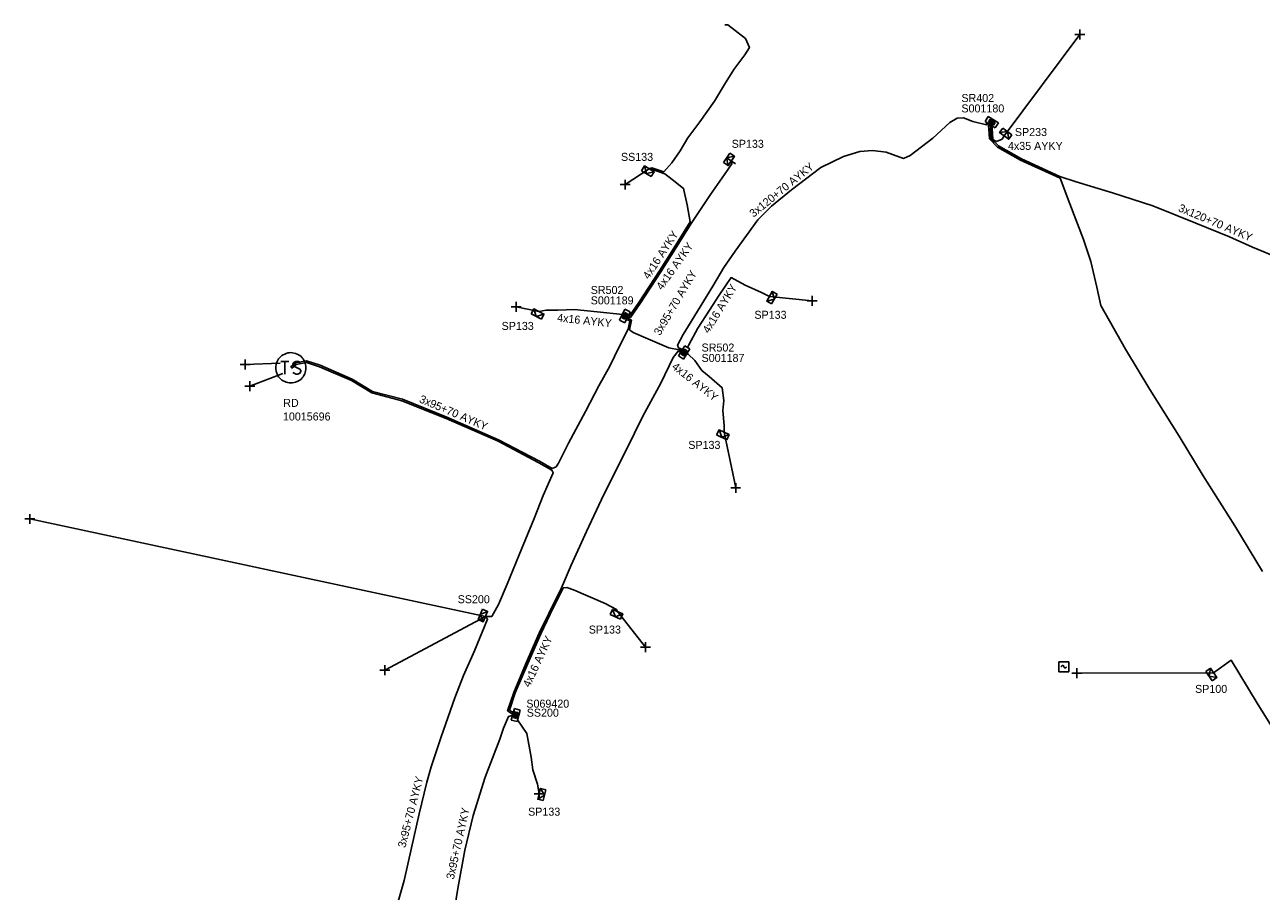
# Model space of a CAD drawing. Extents: x -763093 to -760976, y -1155572 to -1152009.
# Drawn here: x -761820.6 to -761666.2, y -1152363.5 to -1152255.3 of the extents above; entities that cross this region are included whole.
import ezdxf

# ---------------------------------------------------------------- set-up
doc = ezdxf.new("R2010")
doc.units = 0
for name, color, linetype in [('Vrstva 1', 7, 'Continuous'), ('Vrstva 25', 7, 'Continuous'), ('Vrstva 26', 7, 'Continuous'), ('Vrstva 27', 7, 'Continuous'), ('Vrstva 28', 7, 'Continuous'), ('Vrstva 29', 7, 'Continuous'), ('Vrstva 30', 7, 'Continuous'), ('Vrstva 31', 7, 'Continuous'), ('Vrstva 33', 7, 'Continuous'), ('Vrstva 34', 7, 'Continuous'), ('Vrstva 5', 7, 'Continuous'), ('Vrstva 52', 7, 'Continuous'), ('Vrstva 54', 7, 'Continuous'), ('Vrstva 59', 7, 'Continuous'), ('Vrstva 6', 7, 'Continuous'), ('Vrstva 8', 7, 'Continuous'), ('Vrstva 9', 7, 'Continuous')]:
    doc.layers.add(name, color=color, linetype=linetype)

# ---------------------------------------------------------------- blocks, each defined once
blk = doc.blocks.new('NN800')
at = {"layer": 'Vrstva 1'}
for points in [[(-0.44, 0.44), (0.44, -0.44)], [(-0.44, -0.44), (0.44, 0.44)]]:
    blk.add_lwpolyline(points, dxfattribs=at)
blk = doc.blocks.new('NN620')
at = {"layer": 'Vrstva 8'}
for points in [[(0.75, 0), (-0.75, 0)], [(-0.75, 0), (-0.75, -0.75)], [(0.75, -0.75), (0.75, 0)], [(-0.75, -0.75), (0.75, -0.75)], [(0.37, -0.18), (-0.38, -0.18)], [(-0.38, -0.18), (-0.38, -0.56)], [(-0.38, -0.56), (0.37, -0.56)], [(0.32, -0.23), (-0.33, -0.23)], [(-0.33, -0.23), (-0.33, -0.51)], [(-0.33, -0.51), (0.32, -0.51)], [(0.27, -0.27), (-0.28, -0.27)], [(-0.28, -0.27), (-0.28, -0.46)], [(-0.28, -0.46), (0.27, -0.46)], [(0.23, -0.32), (-0.23, -0.32)], [(-0.23, -0.32), (-0.23, -0.42)], [(-0.23, -0.42), (0.23, -0.42)], [(-0.19, -0.37), (0.19, -0.37)], [(0.23, -0.42), (0.23, -0.32)], [(0.27, -0.46), (0.27, -0.27)], [(0.32, -0.51), (0.32, -0.23)], [(0.37, -0.56), (0.37, -0.18)]]:
    blk.add_lwpolyline(points, dxfattribs=at)
blk = doc.blocks.new('NN630')
at = {"layer": 'Vrstva 9'}
for points in [[(0, -0.7), (-0.7, 0)], [(-0.7, -0.7), (-0.7, 0), (0.7, 0), (0.7, -0.7)], [(-0.7, -0.7), (0.7, -0.7)], [(0, -0.7), (0.7, 0)]]:
    blk.add_lwpolyline(points, dxfattribs=at)
blk = doc.blocks.new('NN740')
at = {"layer": 'Vrstva 1'}
for points in [[(0.62, 0.62), (-0.63, 0.62)], [(-0.63, 0.62), (-0.63, -0.63)], [(0, 0), (0, 0.01), (0, 0.03), (-0.01, 0.05), (-0.01, 0.06), (-0.02, 0.08), (-0.03, 0.09), (-0.04, 0.1), (-0.05, 0.11), (-0.06, 0.12), (-0.08, 0.13), (-0.09, 0.14), (-0.11, 0.14), (-0.12, 0.15), (-0.14, 0.15), (-0.15, 0.15), (-0.17, 0.15), (-0.18, 0.15), (-0.2, 0.15), (-0.21, 0.14), (-0.23, 0.13), (-0.24, 0.12), (-0.26, 0.11), (-0.27, 0.1), (-0.28, 0.09), (-0.29, 0.08), (-0.29, 0.06), (-0.3, 0.05), (-0.3, 0.03), (-0.31, 0.02), (-0.31, 0), (-0.31, 0)], [(0.62, -0.63), (0.62, 0.62)], [(-0.63, -0.63), (0.62, -0.63)], [(0, 0), (0, -0.02), (0, -0.03), (0.01, -0.05), (0.01, -0.06), (0.02, -0.08), (0.03, -0.09), (0.04, -0.1), (0.05, -0.11), (0.06, -0.12), (0.07, -0.13), (0.09, -0.14), (0.1, -0.15), (0.12, -0.15), (0.13, -0.15), (0.15, -0.15), (0.16, -0.15), (0.18, -0.15), (0.19, -0.15), (0.21, -0.14), (0.22, -0.14), (0.24, -0.13), (0.25, -0.12), (0.26, -0.11), (0.27, -0.09), (0.28, -0.08), (0.29, -0.07), (0.29, -0.05), (0.3, -0.04), (0.3, -0.02), (0.3, -0.01), (0.3, -0.01)]]:
    blk.add_lwpolyline(points, dxfattribs=at)
blk = doc.blocks.new('NN610')
at = {"layer": 'Vrstva 6'}
for points in [[(1.88, 0), (1.87, 0.2), (1.84, 0.39), (1.79, 0.58), (1.72, 0.77), (1.63, 0.94), (1.52, 1.11), (1.4, 1.26), (1.26, 1.4), (1.1, 1.53), (0.94, 1.63), (0.76, 1.72), (0.58, 1.8), (0.19, 1.88), (0.19, 1.88), (-0.01, 1.89), (-0.21, 1.88), (-0.4, 1.85), (-0.59, 1.8), (-0.78, 1.72), (-0.95, 1.63), (-1.12, 1.53), (-1.27, 1.4), (-1.41, 1.26), (-1.54, 1.11), (-1.64, 0.94), (-1.73, 0.77), (-1.8, 0.58), (-1.86, 0.39), (-1.89, 0.2), (-1.9, 0), (-1.89, -0.2), (-1.86, -0.39), (-1.8, -0.58), (-1.73, -0.77), (-1.64, -0.95), (-1.54, -1.11), (-1.41, -1.27), (-1.27, -1.41), (-1.12, -1.53), (-0.95, -1.64), (-0.78, -1.73), (-0.59, -1.8), (-0.4, -1.85), (-0.21, -1.88), (-0.01, -1.89), (0.19, -1.88), (0.39, -1.85), (0.58, -1.8), (0.76, -1.73), (0.94, -1.64), (1.1, -1.53), (1.26, -1.41), (1.4, -1.27), (1.52, -1.11), (1.63, -0.95), (1.72, -0.77), (1.79, -0.58), (1.84, -0.39), (1.87, -0.2), (1.88, 0)], [(-1.27, 0.78), (-0.26, 0.78)], [(-0.76, 0.78), (-0.76, -0.79)], [(1.19, 0.66), (0.94, 0.78), (0.62, 0.78), (0.37, 0.66), (0.24, 0.47), (0.24, 0.4), (0.37, 0.22), (1.12, -0.16), (1.25, -0.32), (1.25, -0.48), (1.12, -0.67), (0.87, -0.79), (0.62, -0.79), (0.49, -0.73), (0.24, -0.6)]]:
    blk.add_lwpolyline(points, dxfattribs=at)

msp = doc.modelspace()

# ---------------------------------------------------------------- linework, layer by layer
at = {"layer": 'Vrstva 5'}
for points in [[(-761700.49, -1152267.45), (-761700.47, -1152267.79), (-761702.2, -1152267.36), (-761703.36, -1152266.92), (-761704.13, -1152266.93), (-761705.05, -1152267.48), (-761707.19, -1152269.46), (-761710, -1152271.63), (-761710.83, -1152271.97), (-761713, -1152271.21), (-761714.72, -1152270.98), (-761716.3, -1152271.09), (-761718.33, -1152271.73), (-761721.19, -1152273.11), (-761724.84, -1152275.9), (-761727.33, -1152277.93), (-761729.06, -1152279.66), (-761731.86, -1152283.56), (-761733.3, -1152285.61), (-761734.68, -1152287.93), (-761736.24, -1152290.51), (-761738.37, -1152293.96), (-761739.06, -1152295.29), (-761738.95, -1152295.64), (-761738.45, -1152295.83)], [(-761665.98, -1152323.54), (-761669.44, -1152317.85), (-761673.42, -1152311.6), (-761676.42, -1152306.66), (-761680.09, -1152300.84), (-761683.11, -1152295.81), (-761686.2, -1152290.34), (-761686.68, -1152288.06), (-761687.44, -1152284.83), (-761688.36, -1152282.1), (-761690.08, -1152277.64), (-761691.29, -1152274.44), (-761696.22, -1152272.19), (-761699.11, -1152270.55), (-761700.09, -1152269.52), (-761700.18, -1152268.26), (-761700.25, -1152267.62)], [(-761660.25, -1152285.76), (-761661.13, -1152285.42), (-761663.93, -1152284.42), (-761667.23, -1152283.04), (-761670.12, -1152281.75), (-761674.31, -1152280.06), (-761679.7, -1152277.9), (-761684.72, -1152276.28), (-761689.26, -1152274.88), (-761691.3, -1152274.22), (-761696.12, -1152272.01), (-761698.99, -1152270.39), (-761699.89, -1152269.51), (-761699.98, -1152268.24), (-761700.03, -1152267.76)], [(-761699.81, -1152267.9), (-761699.78, -1152268.22), (-761699.68, -1152269.62), (-761699.24, -1152269.87), (-761698.52, -1152269.57), (-761698.27, -1152269.17)], [(-761745.28, -1152291.72), (-761744.97, -1152291.84), (-761743.73, -1152290.1), (-761741.18, -1152286.12), (-761739.58, -1152283.63), (-761737.38, -1152280.1), (-761734.95, -1152276.5), (-761733.21, -1152273.98), (-761732.29, -1152272.64), (-761732.35, -1152272.29)], [(-761745.19, -1152291.54), (-761745.05, -1152291.6), (-761743.89, -1152289.98), (-761741.34, -1152286.02), (-761739.74, -1152283.53), (-761737.49, -1152279.9), (-761737.87, -1152277.79), (-761738.31, -1152275.71), (-761739.75, -1152274.62), (-761740.65, -1152273.88), (-761742.32, -1152273.33), (-761742.6, -1152273.28)], [(-761737.85, -1152295.65), (-761737.66, -1152295.25), (-761736.53, -1152293.17), (-761735.06, -1152290.94), (-761733.87, -1152289.03), (-761732.39, -1152286.85), (-761730.61, -1152287.82), (-761728.57, -1152288.73), (-761727.59, -1152289.2)], [(-761756.4, -1152291.09), (-761755.48, -1152290.92), (-761754.03, -1152290.92), (-761751.93, -1152290.82), (-761749.1, -1152291.13), (-761745.91, -1152291.47)], [(-761745.45, -1152292.08), (-761745.03, -1152292.25), (-761745.25, -1152293.28), (-761746.35, -1152295.5), (-761747.55, -1152297.93), (-761748.91, -1152300.37), (-761750.58, -1152303.58), (-761752.7, -1152307.52), (-761753.95, -1152310.05), (-761754.25, -1152310.49), (-761754.74, -1152310.71), (-761756.32, -1152309.8), (-761761.42, -1152307.1), (-761767.91, -1152304.29), (-761773.44, -1152302.03), (-761777.18, -1152301.06), (-761779.7, -1152299.52), (-761783.71, -1152297.8), (-761785.42, -1152297.25), (-761786.78, -1152297.52), (-761787.43, -1152298.04)], [(-761738.56, -1152296), (-761738.88, -1152295.88), (-761740.15, -1152295.62), (-761742.78, -1152294.5), (-761744.63, -1152293.73), (-761745.06, -1152293.37), (-761744.81, -1152292.19), (-761745.36, -1152291.9)], [(-761759.68, -1152341.38), (-761760.31, -1152340.94), (-761759.54, -1152338.65), (-761757.97, -1152334.97), (-761756.35, -1152331.25), (-761755.15, -1152328.79), (-761753.56, -1152325.58), (-761752.36, -1152322.78), (-761750.46, -1152318.55), (-761748.26, -1152313.93), (-761745.48, -1152308.41), (-761743.41, -1152304.17), (-761741.18, -1152300.05), (-761739.64, -1152296.84), (-761739.01, -1152296.04), (-761738.67, -1152296.17)], [(-761733.26, -1152306.17), (-761733.25, -1152305.33), (-761733.41, -1152303.46), (-761733.31, -1152302.2), (-761733.5, -1152300.61), (-761735.12, -1152299.2), (-761736.02, -1152298.46), (-761736.9, -1152297.2), (-761737.74, -1152296.4), (-761737.95, -1152296.3)], [(-761787.31, -1152298.2), (-761786.7, -1152297.7), (-761785.44, -1152297.45), (-761783.79, -1152297.98), (-761779.8, -1152299.7), (-761777.26, -1152301.24), (-761773.5, -1152302.23), (-761767.99, -1152304.47), (-761761.5, -1152307.28), (-761756.42, -1152309.98), (-761754.77, -1152310.92), (-761754.61, -1152311.24), (-761755.85, -1152314.06), (-761756.99, -1152316.96), (-761758.87, -1152321.49), (-761760.35, -1152325.12), (-761761.44, -1152327.69), (-761762.28, -1152329.19), (-761763.07, -1152329.18), (-761762.81, -1152329.5), (-761764.45, -1152333.47), (-761765.81, -1152336.55), (-761766.9, -1152339.35), (-761768.61, -1152344.21), (-761769.86, -1152347.97), (-761770.39, -1152349.87), (-761771.37, -1152353.83), (-761772.32, -1152358.08), (-761773.23, -1152362.16), (-761774.04, -1152365.05)], [(-761634.35, -1152376.55), (-761634.84, -1152376.97), (-761632.99, -1152380.85), (-761633.54, -1152381.11), (-761638.35, -1152386.44), (-761640.07, -1152387.59), (-761640.77, -1152384.25), (-761646.56, -1152375.28), (-761654.67, -1152363.13), (-761655.44, -1152358.33), (-761660.7, -1152349.53), (-761666.67, -1152339.99), (-761669.92, -1152334.61), (-761672.1, -1152336.22)], [(-761763.1, -1152409.21), (-761763.62, -1152409.06), (-761764.16, -1152407.12), (-761765.09, -1152403.58), (-761765.7, -1152401.09), (-761766.51, -1152395.99), (-761767.28, -1152390.32), (-761767.68, -1152386.44), (-761767.97, -1152381.79), (-761768.06, -1152376.91), (-761767.99, -1152373.7), (-761767.96, -1152372.45), (-761767.95, -1152372.23), (-761767.92, -1152372), (-761767.84, -1152371.4), (-761767.25, -1152367.79), (-761766.52, -1152363.16), (-761765.63, -1152358.34), (-761764.62, -1152354.03), (-761763.12, -1152349.26), (-761761.26, -1152344.49), (-761760.81, -1152343.13), (-761760.18, -1152341.66), (-761759.72, -1152341.55)]]:
    msp.add_lwpolyline(points, dxfattribs=at)
at = {"layer": 'Vrstva 52'}
for points in [[(-761759.61, -1152341.17), (-761759.8, -1152341.05), (-761760.07, -1152340.88), (-761759.36, -1152338.72), (-761757.79, -1152335.05), (-761756.17, -1152331.33), (-761754.97, -1152328.87), (-761753.35, -1152325.61), (-761752.89, -1152325.57), (-761752.06, -1152325.85), (-761748.1, -1152327.57), (-761746.71, -1152328.32), (-761746.56, -1152328.57)], [(-761759.07, -1152342.09), (-761757.88, -1152343.77), (-761757.35, -1152346.76), (-761757.15, -1152348.34), (-761756.58, -1152350.11), (-761756.37, -1152351.32)]]:
    msp.add_lwpolyline(points, dxfattribs=at)
at = {"layer": 'Vrstva 59'}
for points in [[(-761698.27, -1152269.17), (-761688.81, -1152256.5)], [(-761742.6, -1152273.28), (-761745.63, -1152275.25)], [(-761727.59, -1152289.2), (-761722.25, -1152289.75)], [(-761756.4, -1152291.09), (-761759.25, -1152290.5)], [(-761788.7, -1152297.53), (-761793.1, -1152297.7)], [(-761788.39, -1152298.83), (-761792.5, -1152300.4)], [(-761733.26, -1152306.17), (-761731.81, -1152313.13)], [(-761763.07, -1152329.18), (-761820, -1152317)], [(-761763.07, -1152329.18), (-761775.63, -1152335.88)], [(-761746.56, -1152328.57), (-761743.06, -1152333)], [(-761672.1, -1152336.22), (-761689.19, -1152336.25)]]:
    msp.add_lwpolyline(points, dxfattribs=at)
at = {"layer": 'Vrstva 9'}
msp.add_lwpolyline([(-761742.6, -1152273.28), (-761742.3, -1152273.13), (-761740.79, -1152273.63), (-761739.79, -1152272.53), (-761738.75, -1152271.01), (-761737.78, -1152269.39), (-761736.29, -1152267.41), (-761734.44, -1152264.81), (-761733.22, -1152262.76), (-761732.02, -1152260.89), (-761730.68, -1152259.02), (-761730.1, -1152258.11), (-761730.59, -1152257.01), (-761732.81, -1152255.3), (-761733.16, -1152255.28)], dxfattribs=at)

# ---------------------------------------------------------------- block references
at = {"layer": 'Vrstva 25'}
msp.add_blockref('NN610', (-761787.37, -1152298.12), dxfattribs=at)
at = {"layer": 'Vrstva 28'}
for p, rotation in [((-761700.03, -1152267.76), 146.82188903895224), ((-761745.32, -1152291.81), -115.79140054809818), ((-761738.56, -1152296), 58.09555281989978), ((-761759.65, -1152341.38), 74.66691113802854)]:
    msp.add_blockref('NN620', p, dxfattribs=dict(at, rotation=rotation))
at = {"layer": 'Vrstva 31'}
for p, rotation in [((-761698.27, -1152269.17), 143.85841118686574), ((-761732.35, -1152272.29), -122.9142305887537), ((-761742.6, -1152273.28), -31.414213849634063), ((-761727.59, -1152289.2), 60.85455840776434), ((-761756.4, -1152291.09), -26.635907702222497), ((-761733.26, -1152306.17), -25.39394379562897), ((-761763.07, -1152329.18), -112.70814999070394), ((-761746.56, -1152328.57), -23.460458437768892), ((-761672.1, -1152336.22), -55.43739168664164), ((-761756.37, -1152351.32), 75.53500412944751)]:
    msp.add_blockref('NN630', p, dxfattribs=dict(at, rotation=rotation))
at = {"layer": 'Vrstva 34'}
for p, rotation in [((-761688.81, -1152256.5), 45), ((-761732.35, -1152272.29), 99.8558834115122), ((-761745.63, -1152275.25), 45), ((-761722.25, -1152289.75), 45), ((-761759.25, -1152290.5), 45), ((-761793.1, -1152297.7), 45.00000009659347), ((-761792.5, -1152300.4), 45), ((-761731.81, -1152313.13), 45), ((-761820, -1152317), 45), ((-761743.06, -1152333), 45), ((-761775.63, -1152335.88), 45), ((-761689.19, -1152336.25), 44.99999995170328), ((-761756.37, -1152351.34), 45)]:
    msp.add_blockref('NN800', p, dxfattribs=dict(at, rotation=rotation))
msp.add_blockref('NN740', (-761690.8, -1152335.44), dxfattribs=at)

# ---------------------------------------------------------------- texts
at = {"layer": 'Vrstva 26'}
msp.add_text('10015696', height=1, dxfattribs=at).set_placement((-761788.37, -1152304.7))
at = {"layer": 'Vrstva 27'}
msp.add_text('RD', height=1, dxfattribs=at).set_placement((-761788.33, -1152303))
at = {"layer": 'Vrstva 29'}
for s, p in [('S001180', (-761703.61, -1152266.23)), ('S001189', (-761749.92, -1152290.2)), ('S001187', (-761736.07, -1152297.39)), ('S069420', (-761757.96, -1152340.56))]:
    msp.add_text(s, height=1, dxfattribs=at).set_placement(p)
at = {"layer": 'Vrstva 30'}
for s, p in [('SR402', (-761703.61, -1152264.93)), ('SR502', (-761749.92, -1152288.9)), ('SR502', (-761736.07, -1152296.09)), ('SS200', (-761757.91, -1152341.69))]:
    msp.add_text(s, height=1, dxfattribs=at).set_placement(p)
at = {"layer": 'Vrstva 33'}
for s, p in [('SP233', (-761696.93, -1152269.18)), ('SP133', (-761732.31, -1152270.65)), ('SS133', (-761746.14, -1152272.28)), ('SP133', (-761729.47, -1152292)), ('SP133', (-761761.05, -1152293.39)), ('SP133', (-761737.73, -1152308.25)), ('SS200', (-761766.54, -1152327.52)), ('SP133', (-761750.16, -1152331.31)), ('SP100', (-761674.42, -1152338.72)), ('SP133', (-761757.74, -1152354.05))]:
    msp.add_text(s, height=1, dxfattribs=at).set_placement(p)
at = {"layer": 'Vrstva 54'}
msp.add_text('4x16 AYKY', height=1, rotation=64.965, dxfattribs=at).set_placement((-761757.55, -1152338.1))
at = {"layer": 'Vrstva 6'}
msp.add_text('4x35 AYKY', height=1, dxfattribs=at).set_placement((-761697.8, -1152270.91))
for s, rotation, p in [('3x120+70 AYKY', 39.148, (-761729.59, -1152279.39)), ('3x120+70 AYKY', 337.159, (-761676.6, -1152278.53)), ('4x16 AYKY', 56.725, (-761742.66, -1152287.15)), ('4x16 AYKY', 54.609, (-761741.01, -1152288.49)), ('3x95+70 AYKY', 59.349, (-761741.25, -1152294.17)), ('4x16 AYKY', 58.351, (-761735.17, -1152293.9)), ('4x16 AYKY', 353.83, (-761754.15, -1152292.33)), ('4x16 AYKY', 321.739, (-761739.87, -1152298.14)), ('3x95+70 AYKY', 336.901, (-761771.43, -1152302.39)), ('3x95+70 AYKY', 75.601, (-761773.08, -1152358.13)), ('3x95+70 AYKY', 77.512, (-761767.02, -1152362.07))]:
    msp.add_text(s, height=1, rotation=rotation, dxfattribs=at).set_placement(p)

doc.saveas('drawing.dxf')
